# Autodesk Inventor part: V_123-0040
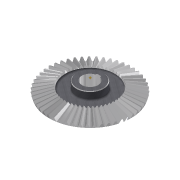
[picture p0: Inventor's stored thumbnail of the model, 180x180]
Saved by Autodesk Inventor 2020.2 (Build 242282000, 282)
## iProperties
+MSCProtocol1+ProtocolID: P00060228092509906
+MSCProtocol2+Protocol: P00060228092509906<@PID>[Version]<@EL>Version=2.2<@EL>[Main]<@EL>VarLists=A,B,C,D,E,F,K<@EL>PartKey=Gears<@EL>Standard=DIN<@EL>View=MODELB<@EL>DataFile=SPIDATA|
Manager: www.cadconsulting.pl
Company: Fabian Stasiak CAD Consulting
Shininess: 20.0
Length Units: 11269
Angle Units: 11279
Time Units: 11290
Mass Units: 11283
Length Display Precision: 3
Angle Display Precision: 2
Created: 2001-01
Part Number: V_123-0040
Material: Stal 60
Document SubType Name: Modeling
Description: Koło zęb. stożkowe z=51
Project: Przekładnia X51
Designer: F.Stasiak
Mass: 1037.29 g
Surface Area: 571.297 cm^2
Volume: 132.139 cm^3
Density: 7.85 g/cm^3
Appearance: Chrom
Density: 7.86
Volumn: 5.864026952018771
Area: 31.42094824814569
PropertySet Name: Model Information
Control State: 0
Master: False
Checked Out: False
TAB_mte: 3
TAB_z1: 15
TAB_z2: 51
TAB_betam: 20
TAB_x: 0.1632
TAB_xt: 0
TAB_delta1: 16.3895
TAB_delta2: 73.6105
TAB_IT: 6e26
TAB_fpt1: ±0.01
TAB_fpt2: ±0.011
TAB_tfa: 0
TAB_sk1: 4.305
TAB_sk2: 3.699
TAB_ECs1: -0.03
TAB_ECd1: -0.08
TAB_ECs2: -0.04
TAB_ECd2: -0.1
TAB_hk1: 2.706
TAB_hk2: 1.837
TAB_omega: 90
TAB_de1: 45
TAB_de2: 153
TAB_le: 79.74
TAB_deltaf1: 14.1558
TAB_deltaf2: 70.6745
TAB_alfat: 20
Author: F.Stasiak
Subject: Zbiór ćwiczeń. Autodesk Inventor 2020. Kurs podstawowy
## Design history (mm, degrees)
node "Bryła1"
node "Korpusy bryłowe"
node "Korpusy powierzchniowe"
revolve "Base Body" stored, may be unused: angle "d10" = 360 deg
node "Tooth Plane"
workpoint "Work Point"
sketch "Sketch2"
  geometry: L1 (4.216, 3.832)-(-4.216, 3.832); L2 (0, -6.728)-(4.216, 3.832); L3 (-4.216, 3.832)-(0, -6.728); L4 (0, 2.5)-(0, -3) reference; L5 (0, 2.5)-(0, -3) reference; L6 (0, 2.5)-(0, -3) reference; L7 (0, -73.314)-(0, 27.014) reference; L8 (0, -73.314)-(0, 27.014) reference; L9 (92.65, -15.24)-(-123.534, -15.24) reference; A1 r 6.122 centre (0, -0.607) between (-4.216, 3.832) and (0, -6.728); 1 further point; 1 other entity
  constraints: 6 end point, 3 point on circle, 2 point on line, 1 centre point, 1 horizontal, 1 vertical alignment, 1 other
  dimensions: "d42" = 43.5294 deg angle of L3 L2 (= msp_a2); "d43" = 10.56 distance from line of L2.start L1 (= 1.6 x msp_he); "d54" = 12.54559 distance of L2.start point (0, -19.274) (= msp_y)
extrude "Tooth" cut sketch "Sketch2" distance "d18" = 32.436 (= 1.02 x prf_b); taper "d19" = -1.88111 deg (= msp_a1)
pattern_circular "Tooth Pattern" dims angle "d22" = 360 deg
revolve "Fix Body" stored, may be unused: angle "d23" = 360 deg
sketch "Sketch7"
  geometry: L1 (-28.8, 0)-(38.4, 0) reference; L2 (0, -28.8)-(0, 38.4) reference; 2 further points
  constraints: 1 coincident
hole "Hole" sketch "Sketch7" diameter "d47" = 37.673 (= hole); stored, may be unused: countersink angle "d51" = 60 deg, drill point angle "d53" = 118 deg; dims "d48" = 6, "d49" = 4, "d50" = 2, "d52" = 8
node "Gear Axis"
node "Mesh Plane"
node "Intersection"
sketch "Szkic8"
  geometry: C1 r 25 at (0, 0); A1 r 45.298 centre (0, 0) between (32.114, -31.947) and (32.921, -31.115) reference; A2 r 45.298 centre (0, 0) between (32.921, -31.115) and (35.797, -27.759) reference; A3 r 45.298 centre (0, 0) between (35.797, -27.759) and (36.495, -26.833) reference; A4 r 45.298 centre (0, 0) between (36.495, -26.833) and (38.936, -23.149) reference; A5 r 45.298 centre (0, 0) between (38.936, -23.149) and (39.516, -22.145) reference; A6 r 45.298 centre (0, 0) between (39.516, -22.145) and (41.486, -18.189) reference; A7 r 45.298 centre (0, 0) between (41.486, -18.189) and (41.938, -17.121) reference; A8 r 45.298 centre (0, 0) between (41.938, -17.121) and (43.407, -12.953) reference; A9 r 45.298 centre (0, 0) between (43.407, -12.953) and (43.724, -11.838) reference; A10 r 45.298 centre (0, 0) between (43.724, -11.838) and (44.67, -7.521) reference; A11 r 45.298 centre (0, 0) between (44.67, -7.521) and (44.847, -6.375) reference; A12 r 45.298 centre (0, 0) between (44.847, -6.375) and (45.255, -1.974) reference; A13 r 45.298 centre (0, 0) between (45.255, -1.974) and (45.291, -0.815) reference; A14 r 45.298 centre (0, 0) between (45.291, -0.815) and (45.155, 3.602) reference; A15 r 45.298 centre (0, 0) between (45.155, 3.602) and (45.048, 4.756) reference; A16 r 45.298 centre (0, 0) between (45.048, 4.756) and (44.37, 9.124) reference; A17 r 45.298 centre (0, 0) between (44.37, 9.124) and (44.122, 10.256) reference; A18 r 45.298 centre (0, 0) between (44.122, 10.256) and (42.912, 14.507) reference; A19 r 45.298 centre (0, 0) between (42.912, 14.507) and (42.527, 15.601) reference; A20 r 45.298 centre (0, 0) between (42.527, 15.601) and (40.804, 19.671) reference; A21 r 45.298 centre (0, 0) between (40.804, 19.671) and (40.288, 20.708) reference; A22 r 45.298 centre (0, 0) between (40.288, 20.708) and (38.078, 24.536) reference; A23 r 45.298 centre (0, 0) between (38.078, 24.536) and (37.437, 25.502) reference; A24 r 45.298 centre (0, 0) between (37.437, 25.502) and (34.774, 29.029) reference; A25 r 45.298 centre (0, 0) between (34.774, 29.029) and (34.02, 29.91) reference; A26 r 45.298 centre (0, 0) between (34.02, 29.91) and (30.943, 33.083) reference; A27 r 45.298 centre (0, 0) between (30.943, 33.083) and (30.086, 33.864) reference; A28 r 45.298 centre (0, 0) between (30.086, 33.864) and (26.643, 36.634) reference; A29 r 45.298 centre (0, 0) between (26.643, 36.634) and (25.697, 37.304) reference; A30 r 45.298 centre (0, 0) between (25.697, 37.304) and (21.939, 39.631) reference; A31 r 45.298 centre (0, 0) between (21.939, 39.631) and (20.918, 40.179) reference; A32 r 45.298 centre (0, 0) between (20.918, 40.179) and (16.903, 42.027) reference; A33 r 45.298 centre (0, 0) between (16.903, 42.027) and (15.822, 42.445) reference; A34 r 45.298 centre (0, 0) between (15.822, 42.445) and (11.61, 43.785) reference; A35 r 45.298 centre (0, 0) between (11.61, 43.785) and (10.486, 44.068) reference; A36 r 45.298 centre (0, 0) between (10.486, 44.068) and (6.141, 44.88) reference; A37 r 45.298 centre (0, 0) between (6.141, 44.88) and (4.991, 45.023) reference; A38 r 45.298 centre (0, 0) between (4.991, 45.023) and (0.58, 45.295) reference; A39 r 45.298 centre (0, 0) between (0.58, 45.295) and (-0.58, 45.295) reference; A40 r 45.298 centre (0, 0) between (-0.58, 45.295) and (-4.991, 45.023) reference; A41 r 45.298 centre (0, 0) between (-4.991, 45.023) and (-6.141, 44.88) reference; A42 r 45.298 centre (0, 0) between (-6.141, 44.88) and (-10.486, 44.068) reference; A43 r 45.298 centre (0, 0) between (-10.486, 44.068) and (-11.61, 43.785) reference; A44 r 45.298 centre (0, 0) between (-11.61, 43.785) and (-15.822, 42.445) reference; A45 r 45.298 centre (0, 0) between (-15.822, 42.445) and (-16.903, 42.027) reference; A46 r 45.298 centre (0, 0) between (-16.903, 42.027) and (-20.918, 40.179) reference; A47 r 45.298 centre (0, 0) between (-20.918, 40.179) and (-21.939, 39.631) reference; A48 r 45.298 centre (0, 0) between (-21.939, 39.631) and (-25.697, 37.304) reference; A49 r 45.298 centre (0, 0) between (-25.697, 37.304) and (-26.643, 36.634) reference; A50 r 45.298 centre (0, 0) between (-26.643, 36.634) and (-30.086, 33.864) reference; A51 r 45.298 centre (0, 0) between (-30.086, 33.864) and (-30.943, 33.083) reference; A52 r 45.298 centre (0, 0) between (-30.943, 33.083) and (-34.02, 29.91) reference; A53 r 45.298 centre (0, 0) between (-34.02, 29.91) and (-34.774, 29.029) reference; A54 r 45.298 centre (0, 0) between (-34.774, 29.029) and (-37.437, 25.502) reference; A55 r 45.298 centre (0, 0) between (-37.437, 25.502) and (-38.078, 24.536) reference; A56 r 45.298 centre (0, 0) between (-38.078, 24.536) and (-40.288, 20.708) reference; A57 r 45.298 centre (0, 0) between (-40.288, 20.708) and (-40.804, 19.671) reference; A58 r 45.298 centre (0, 0) between (-40.804, 19.671) and (-42.527, 15.601) reference; A59 r 45.298 centre (0, 0) between (-42.527, 15.601) and (-42.912, 14.507) reference; A60 r 45.298 centre (0, 0) between (-42.912, 14.507) and (-44.122, 10.256) reference; A61 r 45.298 centre (0, 0) between (-44.122, 10.256) and (-44.37, 9.124) reference; A62 r 45.298 centre (0, 0) between (-44.37, 9.124) and (-45.048, 4.756) reference; A63 r 45.298 centre (0, 0) between (-45.048, 4.756) and (-45.155, 3.602) reference; A64 r 45.298 centre (0, 0) between (-45.155, 3.602) and (-45.291, -0.815) reference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
  constraints: 1 centre point, 1 coincident
  dimensions: "d69" = 50 diameter of C1
extrude "Wyciągnięcie proste2" join sketch "Szkic8" distance "d70" = 12; taper "d71" = 0 deg
sketch "Szkic9"
  geometry: C1 r 25 at (0, 0); A1 r 75.346 centre (0, 0) between (65.772, -36.758) and (68.969, -30.335) reference; A2 r 75.346 centre (0, 0) between (68.969, -30.335) and (69.79, -28.397) reference; A3 r 75.346 centre (0, 0) between (69.79, -28.397) and (72.175, -21.63) reference; A4 r 75.346 centre (0, 0) between (72.175, -21.63) and (72.751, -19.605) reference; A5 r 75.346 centre (0, 0) between (72.751, -19.605) and (74.286, -12.597) reference; A6 r 75.346 centre (0, 0) between (74.286, -12.597) and (74.609, -10.516) reference; A7 r 75.346 centre (0, 0) between (74.609, -10.516) and (75.27, -3.372) reference; A8 r 75.346 centre (0, 0) between (75.27, -3.372) and (75.335, -1.268) reference; A9 r 75.346 centre (0, 0) between (75.335, -1.268) and (75.114, 5.903) reference; A10 r 75.346 centre (0, 0) between (75.114, 5.903) and (74.92, 8) reference; A11 r 75.346 centre (0, 0) between (74.92, 8) and (73.82, 15.089) reference; A12 r 75.346 centre (0, 0) between (73.82, 15.089) and (73.369, 17.146) reference; A13 r 75.346 centre (0, 0) between (73.369, 17.146) and (71.406, 24.046) reference; A14 r 75.346 centre (0, 0) between (71.406, 24.046) and (70.706, 26.032) reference; A15 r 75.346 centre (0, 0) between (70.706, 26.032) and (67.91, 32.639) reference; A16 r 75.346 centre (0, 0) between (67.91, 32.639) and (66.971, 34.524) reference; A17 r 75.346 centre (0, 0) between (66.971, 34.524) and (63.384, 40.737) reference; A18 r 75.346 centre (0, 0) between (63.384, 40.737) and (62.221, 42.492) reference; A19 r 75.346 centre (0, 0) between (62.221, 42.492) and (57.897, 48.217) reference; A20 r 75.346 centre (0, 0) between (57.897, 48.217) and (56.528, 49.816) reference; A21 r 75.346 centre (0, 0) between (56.528, 49.816) and (51.533, 54.967) reference; A22 r 75.346 centre (0, 0) between (51.533, 54.967) and (49.977, 56.385) reference; A23 r 75.346 centre (0, 0) between (49.977, 56.385) and (44.388, 60.883) reference; A24 r 75.346 centre (0, 0) between (44.388, 60.883) and (42.67, 62.099) reference; A25 r 75.346 centre (0, 0) between (42.67, 62.099) and (36.57, 65.876) reference; A26 r 75.346 centre (0, 0) between (36.57, 65.876) and (34.715, 66.872) reference; A27 r 75.346 centre (0, 0) between (34.715, 66.872) and (28.197, 69.871) reference; A28 r 75.346 centre (0, 0) between (28.197, 69.871) and (26.234, 70.631) reference; A29 r 75.346 centre (0, 0) between (26.234, 70.631) and (19.397, 72.806) reference; A30 r 75.346 centre (0, 0) between (19.397, 72.806) and (17.355, 73.32) reference; A31 r 75.346 centre (0, 0) between (17.355, 73.32) and (10.303, 74.638) reference; A32 r 75.346 centre (0, 0) between (10.303, 74.638) and (8.214, 74.897) reference; A33 r 75.346 centre (0, 0) between (8.214, 74.897) and (1.053, 75.339) reference; A34 r 75.346 centre (0, 0) between (1.053, 75.339) and (-1.053, 75.339) reference; A35 r 75.346 centre (0, 0) between (-1.053, 75.339) and (-8.214, 74.897) reference; A36 r 75.346 centre (0, 0) between (-8.214, 74.897) and (-10.303, 74.638) reference; A37 r 75.346 centre (0, 0) between (-10.303, 74.638) and (-17.355, 73.32) reference; A38 r 75.346 centre (0, 0) between (-17.355, 73.32) and (-19.397, 72.806) reference; A39 r 75.346 centre (0, 0) between (-19.397, 72.806) and (-26.234, 70.631) reference; A40 r 75.346 centre (0, 0) between (-26.234, 70.631) and (-28.197, 69.871) reference; A41 r 75.346 centre (0, 0) between (-28.197, 69.871) and (-34.715, 66.872) reference; A42 r 75.346 centre (0, 0) between (-34.715, 66.872) and (-36.57, 65.876) reference; A43 r 75.346 centre (0, 0) between (-36.57, 65.876) and (-42.67, 62.099) reference; A44 r 75.346 centre (0, 0) between (-42.67, 62.099) and (-44.388, 60.883) reference; A45 r 75.346 centre (0, 0) between (-44.388, 60.883) and (-49.977, 56.385) reference; A46 r 75.346 centre (0, 0) between (-49.977, 56.385) and (-51.533, 54.967) reference; A47 r 75.346 centre (0, 0) between (-51.533, 54.967) and (-56.528, 49.816) reference; A48 r 75.346 centre (0, 0) between (-56.528, 49.816) and (-57.897, 48.217) reference; A49 r 75.346 centre (0, 0) between (-57.897, 48.217) and (-62.221, 42.492) reference; A50 r 75.346 centre (0, 0) between (-62.221, 42.492) and (-63.384, 40.737) reference; A51 r 75.346 centre (0, 0) between (-63.384, 40.737) and (-66.971, 34.524) reference; A52 r 75.346 centre (0, 0) between (-66.971, 34.524) and (-67.91, 32.639) reference; A53 r 75.346 centre (0, 0) between (-67.91, 32.639) and (-70.706, 26.032) reference; A54 r 75.346 centre (0, 0) between (-70.706, 26.032) and (-71.406, 24.046) reference; A55 r 75.346 centre (0, 0) between (-71.406, 24.046) and (-73.369, 17.146) reference; A56 r 75.346 centre (0, 0) between (-73.369, 17.146) and (-73.82, 15.089) reference; A57 r 75.346 centre (0, 0) between (-73.82, 15.089) and (-74.92, 8) reference; A58 r 75.346 centre (0, 0) between (-74.92, 8) and (-75.114, 5.903) reference; A59 r 75.346 centre (0, 0) between (-75.114, 5.903) and (-75.335, -1.268) reference; A60 r 75.346 centre (0, 0) between (-75.335, -1.268) and (-75.27, -3.372) reference; A61 r 75.346 centre (0, 0) between (-75.27, -3.372) and (-74.609, -10.516) reference; A62 r 75.346 centre (0, 0) between (-74.609, -10.516) and (-74.286, -12.597) reference; A63 r 75.346 centre (0, 0) between (-74.286, -12.597) and (-72.751, -19.605) reference; A64 r 75.346 centre (0, 0) between (-72.751, -19.605) and (-72.175, -21.63) reference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
  constraints: 1 centre point, 1 coincident
  dimensions: "d72" = 50 diameter of C1
extrude "Wyciągnięcie proste3" join sketch "Szkic9" distance "d73" = 12; taper "d74" = 0 deg
revolve "Obrót3" stored, may be unused: angle "d78" = 90 deg
sketch "Szkic11"
  geometry: C1 r 25 at (0, 0) reference
hole "Otwór3" sketch "Szkic11" diameter "d79" = 30; stored, may be unused: countersink angle "d83" = 90 deg, drill point angle "d85" = 118 deg; dims "d80" = 6, "d81" = 4, "d82" = 2, "d84" = 8
fillet "Zaokrąglenie1" dims "d86" = 3
chamfer "Faza1" distance "d87" = 1; stored, may be unused: second distance "d88" = 2, angle "d89" = 45 deg
sketch "Szkic12"
  geometry: L1 (4, 14.457)-(4, 10.9) reference; L2 (-4, 14.457)-(-4, 10.9) reference; L3 (-4, 14.457)-(-4, 16.9); L4 (-4, 16.9)-(4, 16.9); L5 (4, 16.9)-(4, 10.9); L6 (-4, 10.9)-(-4, 14.457); L7 (-4, 10.9)-(4, 10.9); C1 r 24 at (0, 0) reference; 1 further point
  constraints: 10 end point, 2 parallel, 2 perpendicular, 1 collinear, 2 other
  dimensions: "d95" = 6 distance of L4.end L1.end
extrude "Wyciągnięcie proste4" cut sketch "Szkic12" extent not by distance; stored distance "d92" = 12; taper "d93" = 0 deg
sketch "Base Body Sketch"
  geometry: L1 (46.418, 3.807)-(45.298, 0); L2 (46.418, 3.807)-(77.209, -4.205); L3 (77.209, -4.205)-(75.346, -10.537); L4 (-34.121, 0)-(107.571, 0) reference; L5 (45.298, 0)-(0, 0); L6 (0, -10.537)-(75.346, -10.537); L7 (0, 0)-(0, -10.537); L8 (46.418, 3.807)-(0, 15.886); L9 (0, 0)-(0, 15.886); L10 (0, -26.38)-(0, 27.412) reference; L11 (0, 15.886)-(76.5, -6.614); L12 (0, 15.886)-(45.298, 0); L13 (45.298, 0)-(75.346, -10.537)
  constraints: 22 end point, 3 collinear, 2 parallel, 2 perpendicular, 2 point on line
  dimensions: "d33" = 31.8 distance between parallel lines of L3 L1 (= prf_b); "d34" = 154.417 diameter of L2.end L7 (= msp_dae); "d35" = 150.692 diameter of L3.end L7 (= msp_dfe); "d37" = 79.74 distance from line of L3 L8.end (= prf_le); "d41" = 73.6105 deg angle of L9 L11 (= msp_delta); "d59" = 45.29831 distance of L5.end L1.end (derived)
sketch "Sketch3"
  geometry: L1 (-45.298, 0)-(0, 0); L2 (-75.346, -10.537)-(-45.298, 0); L3 (0, -10.537)-(-75.346, -10.537); L4 (0, 0)-(0, -10.537); L5 (-75.346, -10.537)-(75.346, -10.537) reference; L6 (-45.298, 0)-(45.298, 0) reference; L7 (0, -24.791)-(0, 6.761) reference; 1 further point
  constraints: 8 end point, 2 horizontal, 2 point on line, 1 vertical
  dimensions: "d57" = 150.692 diameter of L2.start L7 (= msp_dfe); "d58" = 0 distance between parallel lines of L7 L4; "d60" = 45.29831 distance of L1.start L1.end (= d59)
node "Pętla rzutowana1"
node "Pętla rzutowana2"
sketch "Szkic10"
  geometry: L1 (0, -25.991)-(0, 22.361) reference; L2 (25, -10.537)-(25, -22.537) reference; L3 (25, 0)-(25, 12) reference; L4 (45.298, 0)-(45.889, 2.009) reference; L5 (76.265, -7.413)-(75.346, -10.537) reference; L6 (3.367, 0)-(7.753, 0) reference; L7 (3.367, 0)-(2.21, 0) reference; L8 (-2.21, 0)-(2.21, 0) reference; L9 (-2.21, 0)-(-3.367, 0) reference; L10 (-7.753, 0)-(-3.367, 0) reference; L11 (-7.753, 0)-(-8.893, 0) reference; L12 (-13.179, 0)-(-8.893, 0) reference; L13 (-13.179, 0)-(-14.284, 0) reference; L14 (-18.405, 0)-(-14.284, 0) reference; L15 (-18.405, 0)-(-19.458, 0) reference; L16 (-23.352, 0)-(-19.458, 0) reference; L17 (-23.352, 0)-(-24.337, 0) reference; L18 (-27.945, 0)-(-24.337, 0) reference; L19 (-27.945, 0)-(-28.848, 0) reference; L20 (-32.114, 0)-(-28.848, 0) reference; L21 (-32.114, 0)-(-32.921, 0) reference; L22 (-35.797, 0)-(-32.921, 0) reference; L23 (-35.797, 0)-(-36.495, 0) reference; L24 (-38.936, 0)-(-36.495, 0) reference; L25 (-38.936, 0)-(-39.516, 0) reference; L26 (-41.486, 0)-(-39.516, 0) reference; L27 (-41.486, 0)-(-41.938, 0) reference; L28 (-43.407, 0)-(-41.938, 0) reference; L29 (-43.407, 0)-(-43.724, 0) reference; L30 (-44.67, 0)-(-43.724, 0) reference; L31 (-44.67, 0)-(-44.847, 0) reference; L32 (-45.255, 0)-(-44.847, 0) reference; L33 (-45.255, 0)-(-45.291, 0) reference; L34 (-45.155, 0)-(-45.291, 0) reference; L35 (-45.155, 0)-(-45.048, 0) reference; L36 (-44.37, 0)-(-45.048, 0) reference; L37 (-44.37, 0)-(-44.122, 0) reference; L38 (-42.912, 0)-(-44.122, 0) reference; L39 (-42.912, 0)-(-42.527, 0) reference; L40 (-40.804, 0)-(-42.527, 0) reference; L41 (-40.804, 0)-(-40.288, 0) reference; L42 (-38.078, 0)-(-40.288, 0) reference; L43 (-38.078, 0)-(-37.437, 0) reference; L44 (-34.774, 0)-(-37.437, 0) reference; L45 (-34.774, 0)-(-34.02, 0) reference; L46 (-30.943, 0)-(-34.02, 0) reference; L47 (-30.943, 0)-(-30.086, 0) reference; L48 (-26.643, 0)-(-30.086, 0) reference; L49 (-26.643, 0)-(-25.697, 0) reference; L50 (-21.939, 0)-(-25.697, 0) reference; L51 (-21.939, 0)-(-20.918, 0) reference; L52 (-16.903, 0)-(-20.918, 0) reference; L53 (-16.903, 0)-(-15.822, 0) reference; L54 (-11.61, 0)-(-15.822, 0) reference; L55 (-11.61, 0)-(-10.486, 0) reference; L56 (-6.141, 0)-(-10.486, 0) reference; L57 (-6.141, 0)-(-4.991, 0) reference; L58 (-25, 0)-(25, 0) reference; L59 (-0.58, 0)-(-4.991, 0) reference; L60 (-0.58, 0)-(0.58, 0) reference; L61 (4.991, 0)-(0.58, 0) reference; L62 (4.991, 0)-(6.141, 0) reference; L63 (10.486, 0)-(6.141, 0) reference; L64 (10.486, 0)-(11.61, 0) reference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
  constraints: 16 end point, 5 perpendicular, 3 parallel
  dimensions: "d90" = 3 distance of L86.end L213.end; "d91" = 3 distance of L218.end L127.start
node "Pętla rzutowana3"
node "Pętla rzutowana4"
node "Pętla rzutowana5"
node "Odniesienie1"
node "Odniesienie2"
node "Pętla rzutowana6"
other parameters: "prf_le" = 79.74 [user parameter; used in 3 equation terms], "prf_delta2" = 12.84746 [user parameter; used in 1 equation term], "prf_he2" = 6.6 [user parameter; used in 1 equation term], "prf_dfe2" = 150.692 [user parameter; used in 1 equation term], "prf_dae2" = 154.417 [user parameter; used in 1 equation term], "prf_de2" = 153 [user parameter; used in 1 equation term], "prf_b" = 31.8 [user parameter; used in 2 equation terms], "prf_omega" = 90 deg [user parameter; used in 1 equation term], "msp_delta" = 73.6105 deg (= prf_delta2) [user parameter; used in 3 equation terms], "msp_he" = 6.6 (= prf_he2) [user parameter; used in 2 equation terms], "msp_dfe" = 150.692 (= prf_dfe2) [user parameter; used in 3 equation terms], "msp_dae" = 154.417 (= prf_dae2) [user parameter; used in 2 equation terms], "msp_de" = 153 (= prf_de2) [user parameter; used in 1 equation term], "hole" = 37.673 (= 0.25 x msp_dfe) [user parameter; used in 1 equation term], "msp_y" = 12.54559 (computed from msp_delta, msp_dae, msp_he) [user parameter; used in 1 equation term], "msp_a1" = -1.88111 deg (computed from msp_de, msp_z, prf_le) [user parameter; used in 1 equation term], "msp_a2" = 43.5294 deg (computed from msp_z) [user parameter; used in 1 equation term], "msp_dist" = 22.49989 (computed from prf_le, msp_delta) [user parameter], "d0" = 3.62545 (derived), "d4" = 38.7702 (derived), "d6" = 32.175 (derived), "d8" = 21.89 (derived), "d12" = 0 (derived), "d14" = -13.24579 (derived), "d16" = 9.83731 (derived), "d40" = 19.14 (derived), "d61" = 90 deg, "d64" = 0, "d65" = 90 deg (= prf_omega), "d66" = 2.94118 (computed from prf_z1, prf_z2), "d67" = 0, "d68" = 0
